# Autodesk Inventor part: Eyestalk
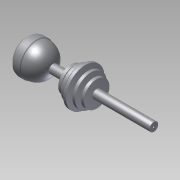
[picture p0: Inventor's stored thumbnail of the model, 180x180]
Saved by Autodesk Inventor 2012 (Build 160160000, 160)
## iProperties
Created: 2012-11
Part Number: Eyestalk
Material: Default
Document SubType Name: Modeling
Designer: TechShop Member
Density: 1 g/cm^3
Author: TechShop Member
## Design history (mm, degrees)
sketch "Eyestalk"
  geometry: L1 (70.427, 19.306)-(149.675, 19.306); L2 (149.675, 19.306)-(149.675, 56.796); L3 (149.675, 56.796)-(162.375, 56.796); L4 (162.375, 56.796)-(162.375, 19.306); L5 (162.375, 19.306)-(175.075, 19.306); L6 (175.075, 19.306)-(175.075, 70.106); L7 (175.075, 70.106)-(187.775, 70.106); L8 (187.775, 70.106)-(187.775, 19.306); L9 (187.775, 19.306)-(200.475, 19.306); L10 (200.475, 19.306)-(200.475, 85.346); L11 (200.475, 85.346)-(213.175, 85.346); L12 (213.175, 85.346)-(213.175, 19.306); L13 (213.175, 19.306)-(225.875, 19.306); L14 (225.875, 19.306)-(225.875, 70.106); L15 (225.875, 70.106)-(238.575, 70.106); L16 (238.575, 70.106)-(238.575, 19.306); L17 (238.575, 19.306)-(251.275, 19.306); L18 (251.275, 19.306)-(251.275, 56.796); L19 (251.275, 56.796)-(263.975, 56.796); L20 (263.975, 56.796)-(263.975, 19.305); L21 (0, 73.025)-(13.97, 73.025); L22 (0, 73.025)-(-2.82, 75.845); L23 (0, 73.025)-(3.988, 73.025); L24 (-2.82, 75.845)-(-27.712, 75.845); L25 (-27.712, 75.845)-(-30.532, 73.025); L26 (-30.532, 73.025)-(-36.882, 73.025); L27 (-36.882, 73.025)-(-19.102, 73.025); L28 (-36.882, 73.025)-(-49.454, 60.453); L29 (-49.454, 60.453)-(-49.454, 47.753); L30 (-49.454, 47.753)-(-44.374, 47.753); L31 (-44.374, 47.753)-(-44.374, 42.673); L32 (-44.374, 42.673)-(-39.294, 42.673); L33 (-39.294, 42.673)-(-39.294, 37.593); L34 (-39.294, 37.593)-(-34.214, 37.593); L35 (-34.214, 37.593)-(-34.214, 32.513); L36 (-34.214, 32.513)-(-24.054, 32.513); L37 (-24.054, 32.513)-(-24.054, 27.433); L38 (-24.054, 27.433)-(-8.814, 27.433); L39 (263.975, 19.305)-(517.975, 19.305); L40 (517.975, 19.305)-(517.975, 0.001); L41 (-8.814, 27.433)-(-8.814, 0.001); L42 (-8.814, 0.001)-(517.975, 0.001); A1 r 73.025 centre (0, 0) between (70.427, 19.306) and (0, 73.025); 3 further points
  constraints: 84 end point, 19 parallel, 15 perpendicular, 4 horizontal, 3 coincident, 2 point on circle, 1 centre point, 1 equal length
  dimensions: "d3" = 73.025 radius of A1; "d4" = 79.248 distance of L1.start L1.end; "d7" = 37.4904 distance of L1.end L2.end; "d8" = 12.7 distance of L2.end L3.end; "d24" = 12.7 distance of L4.end L5.end; "d25" = 50.8 distance of L5.end L6.end; "d26" = 12.7 distance of L6.end L7.end; "d27" = 12.7 distance of L8.end L9.end; "d28" = 66.04 distance of L9.end L10.end; "d29" = 12.7 distance of L10.end L11.end; "d30" = 12.7 distance of L12.end L13.end; "d31" = 50.8 distance of L13.end L14.end; "d32" = 12.7 distance of L14.end L15.end; "d33" = 12.7 distance of L16.end L17.end; "d34" = 37.4904 distance of L17.end L18.end; "d35" = 12.7 distance of L18.end L19.end; "d42" = 3.9878 distance of L21.start L22.end; "d43" = 135 deg angle of L23 L22; "d44" = 24.892 distance of L22.end L24.end; "d45" = 3.9878 distance of L24.end L25.end; "d47" = 6.35 distance of L25.end L26.end; "d53" = 17.78 distance of L26.end L28.end; "d55" = 12.7 distance of L28.end L29.end; "d59" = 5.08 distance of L29.end L30.end; "d60" = 5.08 distance of L30.end L31.end; "d61" = 5.08 distance of L31.end L32.end; "d62" = 5.08 distance of L32.end L33.end; "d63" = 5.08 distance of L33.end L34.end; "d64" = 5.08 distance of L34.end L35.end; "d65" = 10.16 distance of L35.end L36.end; "d66" = 5.08 distance of L36.end L37.end; "d67" = 15.24 distance of L37.end L38.end; "d73" = 254 distance of L20.end L39.end; "d74" = 19.304 distance of L39.end L40.end; "d82" = 27.432 distance of L38.end L41.end
revolve "Revolution4" sketch "Eyestalk" stored, may be unused: angle "d84" = 90 deg
hole "Hole2" diameter "d96" = 5.08; stored, may be unused: countersink angle "d100" = 82 deg, drill point angle "d102" = 118 deg; dims "d94" = 25.4, "d95" = 25.4, "d97" = 19.05, "d98" = 9.525, "d99" = 6.35, "d101" = 25.4
body "Solid4"
